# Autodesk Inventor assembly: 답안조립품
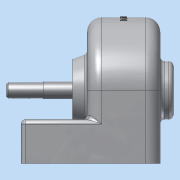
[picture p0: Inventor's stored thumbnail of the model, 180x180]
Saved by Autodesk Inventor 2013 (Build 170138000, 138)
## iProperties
Created: 2015-02
Part Number: 답안조립품
Document SubType Name: Assembly
Designer: Administrator
Author: Administrator
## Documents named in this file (6)
- C:\Documents and Settings\Administrator\바탕 화면\450214V1013\답안조립품.iam
- C:\Documents and Settings\Administrator\바탕 화면\450214V1013\1-본체.ipt
- C:\Documents and Settings\Administrator\바탕 화면\450214V1013\베어링 6001.ipt
- C:\Documents and Settings\Administrator\바탕 화면\450214V1013\축.ipt
- C:\Documents and Settings\Administrator\바탕 화면\450214V1013\키5x5.ipt
- C:\Documents and Settings\Administrator\바탕 화면\450214V1013\5-스퍼기어.ipt
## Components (1 placed, 1 different names)
1. 1-본체:1
